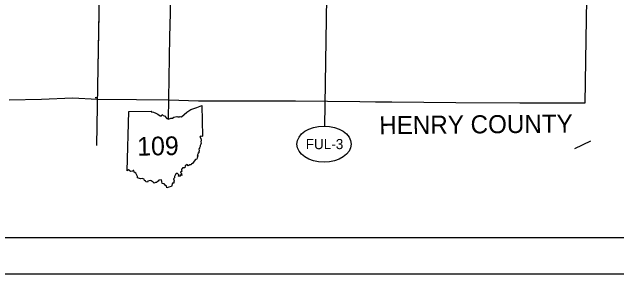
# Model space of a CAD drawing. Extents: x 0 to 849, y 0 to 440.
# Drawn here: x 399.3 to 566.7, y 0 to 72.4 of the extents above; entities that cross this region are included whole.
import ezdxf

# ---------------------------------------------------------------- set-up
doc = ezdxf.new("R2010")
doc.units = 0
for name, color, linetype in [('GM_X_Adjacent_County_Text', 7, 'Continuous'), ('GM_X_County', 7, 'Continuous'), ('GM_X_Interstate_Route', 7, 'Continuous'), ('PV_P_Walk', 7, 'Continuous'), ('RD_X_RR_2', 7, 'Continuous'), ('SH_Border', 7, 'Continuous'), ('SH_Cut_Line', 7, 'Continuous'), ('SH_Data', 7, 'Continuous')]:
    doc.layers.add(name, color=color, linetype=linetype)

msp = doc.modelspace()

# ---------------------------------------------------------------- linework, layer by layer
at = {"layer": 'GM_X_County'}
msp.add_lwpolyline([(558.41, 81.63), (558.09, 64.89), (557.82, 47.22), (539.81, 47.2), (522.1, 47.36), (504.41, 47.52), (499.89, 47.56), (495.53, 47.6), (486.59, 47.67), (477.77, 47.75), (468.99, 47.83), (451.61, 47.8), (450.91, 47.79), (442.65, 48.08), (433.69, 48.15), (422.88, 48.24), (416.03, 48.64), (407.4, 48.26), (398.5, 48.1)], dxfattribs=at)
at = {"layer": 'GM_X_Interstate_Route'}
msp.add_lwpolyline([(442.56, 42.75), (442.94, 65.58), (443.12, 72.11), (443.28, 82.45), (443.42, 82.76), (443.66, 83.03), (444.11, 83.29), (446.92, 83.27), (447.31, 83.42), (447.52, 83.6), (447.77, 83.93), (447.84, 84.2), (447.87, 84.67), (448.07, 94.59), (448.18, 100.95), (448.29, 107.57), (448.4, 115.71), (448.42, 118.04), (448.56, 118.27), (448.73, 118.44), (449.01, 118.57), (449.12, 118.6), (449.72, 118.62), (449.73, 118.62)], dxfattribs=at)
at = {"layer": 'PV_P_Walk'}
msp.add_line((431.11, 28.55), (431.57, 44.92), dxfattribs=at)
for points in [[(431.57, 44.92), (437.92, 45.03), (437.82, 44.83), (438.42, 44.79), (439.06, 44.44), (439.6, 44.22), (440.26, 43.7), (440.65, 43.7), (440.82, 44.13), (441.12, 43.8), (441.48, 43.74), (442.1, 42.96), (442.61, 42.79), (443.22, 43.06), (443.68, 43.1), (444.01, 43.36), (444.88, 43.59), (445.13, 43.46), (445.59, 43.48), (445.82, 43.58), (446.22, 43.49), (446.93, 44.09), (447.66, 44.79), (448.78, 45.45), (450.46, 46.08), (451.78, 46.64), (451.97, 38.15)], [(451.97, 38.15), (451.78, 38.03), (451.47, 38.08), (451.27, 37.84), (451.52, 37.45), (451.64, 37.03), (451.54, 36.56), (451.64, 36.18), (451.57, 35.86), (451.38, 35.54), (451.31, 35.24), (451.15, 34.92), (451.16, 34.74), (451.01, 34.6), (451.04, 34.07), (450.96, 33.77), (450.99, 33.52), (450.73, 33.45), (450.79, 33.24), (450.63, 33.08), (450.67, 32.8), (450.48, 32.62), (450.66, 32.27), (450.52, 32.16), (450.4, 31.72), (450.08, 31.63), (449.43, 30.84), (449.2, 30.54), (448.95, 30.47), (448.81, 30.16), (448.49, 30.16), (448.02, 29.94), (447.71, 30.31), (447.17, 29.87), (447.1, 29.36), (446.42, 29.38), (446.45, 29.12), (446.29, 29.04), (446.16, 28.78), (446.24, 28.32), (445.92, 28.21), (445.96, 27.94), (446.16, 27.78), (446.25, 27.27), (445.91, 27.37), (445.63, 26.94), (445.35, 27.04), (445.44, 27.41), (444.96, 27.84), (444.5, 27.49), (444.26, 26.93), (444.26, 26.56), (443.92, 26.33), (444.13, 25.79), (444.09, 25.43), (444.1, 25.08), (443.67, 25.09), (443.42, 24.15)], [(443.42, 24.15), (442.67, 23.97), (442.16, 23.86), (441.98, 24.29), (441.61, 24.52), (441.37, 24.95), (440.84, 25.01), (440.72, 25.6), (440.66, 26.07), (439.94, 25.96), (439.74, 25.66), (439.48, 25.59), (439.33, 25.29), (438.98, 25.27), (438.61, 25.13), (438.36, 25.42), (437.75, 25.71), (437.47, 25.86), (436.9, 25.62), (436.77, 25.35), (436.31, 25.47), (436.2, 25.78), (435.93, 25.87), (435.87, 26.19), (435.27, 26.37), (434.82, 26.3), (434.01, 26.56), (433.97, 26.99), (433.69, 27.51), (433.55, 27.88), (433.04, 28.15), (432.94, 28.59), (432.78, 28.57), (432.63, 28.4), (432.07, 28.32), (431.84, 28.49), (431.53, 28.8), (431.11, 28.55)]]:
    msp.add_lwpolyline(points, dxfattribs=at)
at = {"layer": 'RD_X_RR_2'}
msp.add_line((422.95, 48.68), (422.28, 48.69), dxfattribs=at)
for points in [[(423.01, 51.86), (425.8, 203.33)], [(423.01, 51.86), (423.39, 72.43)], [(422.7, 35.51), (423.01, 51.86)], [(555.1, 34.74), (559.46, 36.79)]]:
    msp.add_lwpolyline(points, dxfattribs=at)
at = {"layer": 'SH_Border'}
msp.add_lwpolyline([(30, 430), (670, 430), (670, 10), (30, 10)], close=True, dxfattribs=at)
at = {"layer": 'SH_Cut_Line'}
msp.add_lwpolyline([(0, 0), (680, 0), (680, 440), (0, 440)], close=True, dxfattribs=at)
at = {"layer": 'SH_Data'}
msp.add_line((485.83, 40.92), (487.74, 153.62), dxfattribs=at)
msp.add_ellipse((485.64, 35.92), major_axis=(7.5, 0), ratio=0.666667, dxfattribs=at)

# ---------------------------------------------------------------- texts
at = {"layer": 'GM_X_Adjacent_County_Text'}
msp.add_text('HENRY COUNTY', height=5.0058, rotation=0.5197, dxfattribs=at).set_placement((500.94, 38.63))
at = {"layer": 'PV_P_Walk'}
msp.add_text('109', height=5.162, rotation=1.0142, dxfattribs=at).set_placement((433.94, 32.71))
at = {"layer": 'SH_Data'}
msp.add_text('FUL-3', height=2.8, dxfattribs=at).set_placement((480.57, 34.52))

doc.saveas('drawing.dxf')
